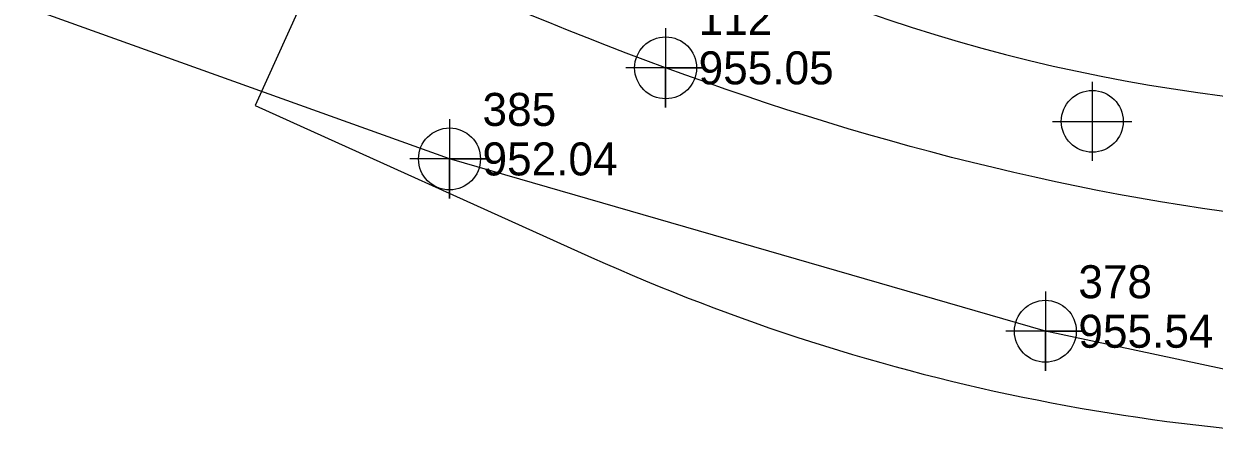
# Model space of a CAD drawing. Extents: x 1150279 to 1151282, y 654632 to 657999.
# Drawn here: x 1150909.2 to 1150999.3, y 657041.1 to 657073.4 of the extents above; entities that cross this region are included whole.
import ezdxf

# ---------------------------------------------------------------- set-up
doc = ezdxf.new("R2010")
doc.units = 0
for name, color, linetype in [('COGO Default Chain', 7, 'Continuous'), ('COGO Default Curve', 7, 'Continuous'), ('Cogo Default Point CELL', 7, 'Continuous'), ('Exist Horizontal Alignment', 7, 'Continuous'), ('Exist Other Culture Fence Line', 7, 'Continuous'), ('Exist Other Culture Fence Line Cogo Elevation', 7, 'Continuous'), ('Exist Other Culture Fence Line Cogo Number', 7, 'Continuous'), ('Exist Other Culture Fence Line Cogo Point CELL', 7, 'Continuous'), ('Exist Right of Way Line', 7, 'Continuous'), ('Exist Roads EOP', 7, 'Continuous'), ('Exist Roads EOP Cogo Elevation', 7, 'Continuous'), ('Exist Roads EOP Cogo Number', 7, 'Continuous'), ('Exist Roads EOP Cogo Point CELL', 7, 'Continuous')]:
    doc.layers.add(name, color=color, linetype=linetype)

msp = doc.modelspace()

# ---------------------------------------------------------------- linework, layer by layer
at = {"layer": 'COGO Default Chain'}
msp.add_arc((1151016.013, 657196.992), 130, 245.68044, 271.91872, dxfattribs=at)
at = {"layer": 'COGO Default Curve'}
msp.add_arc((1151016.013, 657196.992), 130, 245.68044, 271.91872, dxfattribs=at)
at = {"layer": 'Cogo Default Point CELL'}
for points in [[(1150990.085, 657069.051), (1150990.085, 657066.051)], [(1150987.085, 657066.051), (1150990.085, 657066.051)], [(1150990.085, 657066.051), (1150993.085, 657066.051)], [(1150990.085, 657066.051), (1150990.085, 657063.051)]]:
    msp.add_lwpolyline(points, dxfattribs=at)
msp.add_circle((1150990.085, 657066.051), 2.344, dxfattribs=at)
at = {"layer": 'Exist Horizontal Alignment'}
msp.add_arc((1151016.013, 657196.992), 130, 245.68044, 271.91872, dxfattribs=at)
at = {"layer": 'Exist Other Culture Fence Line'}
msp.add_lwpolyline([(1151064.379, 657042.204), (1151035.792, 657039.664), (1150986.531, 657050.151), (1150941.416, 657063.204), (1150898.391, 657078.653), (1150854.858, 657094.995), (1150825.025, 657100.534), (1150812.457, 657091.594), (1150835.172, 657043.741), (1150852.719, 657007.431)], dxfattribs=at)
at = {"layer": 'Exist Other Culture Fence Line Cogo Point CELL'}
for points in [[(1150941.416, 657066.204), (1150941.416, 657060.204), (1150941.416, 657063.204), (1150944.416, 657063.204), (1150938.416, 657063.204)], [(1150986.531, 657053.151), (1150986.531, 657047.151), (1150986.531, 657050.151), (1150989.531, 657050.151), (1150983.531, 657050.151)]]:
    msp.add_lwpolyline(points, dxfattribs=at)
for centre in [(1150941.416, 657063.204), (1150986.531, 657050.151)]:
    msp.add_circle(centre, 2.344, dxfattribs=at)
at = {"layer": 'Exist Right of Way Line'}
for p, q in [((1150930.001, 657074.549), (1150926.706, 657067.259)), ((1150926.706, 657067.259), (1150952.18, 657055.747))]:
    msp.add_line(p, q, dxfattribs=at)
msp.add_arc((1151016.013, 657196.992), 155, 245.68044, 271.91872, dxfattribs=at)
at = {"layer": 'Exist Roads EOP'}
msp.add_spline([(1151056.975, 657058.926), (1151008.048, 657058.299), (1150957.779, 657070.103), (1150911.093, 657090.114), (1150910.091, 657090.545)], degree=3, dxfattribs=at)
at = {"layer": 'Exist Roads EOP Cogo Point CELL'}
msp.add_lwpolyline([(1150957.779, 657073.103), (1150957.779, 657067.103), (1150957.779, 657070.103), (1150960.779, 657070.103), (1150954.779, 657070.103)], dxfattribs=at)
msp.add_circle((1150957.779, 657070.103), 2.344, dxfattribs=at)

# ---------------------------------------------------------------- texts
at = {"layer": 'Exist Other Culture Fence Line Cogo Elevation'}
for s, p in [('952.04', (1150943.916, 657061.954)), ('955.54', (1150989.031, 657048.901))]:
    msp.add_text(s, height=2.5, dxfattribs=at).set_placement(p)
at = {"layer": 'Exist Other Culture Fence Line Cogo Number'}
for s, p in [('385', (1150943.916, 657065.704)), ('378', (1150989.031, 657052.651))]:
    msp.add_text(s, height=2.5, dxfattribs=at).set_placement(p)
at = {"layer": 'Exist Roads EOP Cogo Elevation'}
msp.add_text('955.05', height=2.5, dxfattribs=at).set_placement((1150960.279, 657068.853))
at = {"layer": 'Exist Roads EOP Cogo Number'}
msp.add_text('112', height=2.5, dxfattribs=at).set_placement((1150960.279, 657072.603))

doc.saveas('drawing.dxf')
